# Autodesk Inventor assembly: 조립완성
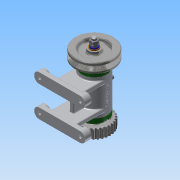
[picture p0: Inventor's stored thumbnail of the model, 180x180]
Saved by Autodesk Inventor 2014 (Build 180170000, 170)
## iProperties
Created: 2015-11
Part Number: 조립완성
Document SubType Name: Assembly
Designer: 27
Author: 27
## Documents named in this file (16)
- C:\Users\27\Desktop\451110V1019\조립완성.iam
- C:\Users\27\Desktop\451110V1019\1-본체.ipt
- C:\Users\27\Desktop\451110V1019\베어링 15 x 32 x 9.ipt
- C:\Users\27\Desktop\451110V1019\축.ipt
- C:\Users\27\Desktop\451110V1019\키 3 x 3 x 12.ipt
- C:\Users\27\Desktop\451110V1019\커버.ipt
- C:\Users\27\Desktop\451110V1019\오일 실 15 25 7.ipt
- C:\Users\27\Desktop\451110V1019\V벨트풀리.ipt
- C:\Users\27\Desktop\451110V1019\스퍼기어.ipt
- C:\Users\27\Desktop\451110V1019\와셔 8x17.ipt
- C:\Users\27\Desktop\451110V1019\스프링와셔 8.ipt
- C:\Users\27\Desktop\451110V1019\너트 M 8.ipt
- C:\Users\27\Desktop\451110V1019\볼트 M4 x 12.ipt
- C:\Users\27\Desktop\451110V1019\니플 M 6 x 0.75.ipt
- C:\Users\27\Desktop\451110V1019\볼트 M 6 x 8.ipt
- C:\Users\27\Desktop\451110V1019\와셔 6x11.5.ipt
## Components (12 placed, 4 different names)
1. 1-본체:1 — 각도:5, 각도:6, 각도:7, 각도:8, 각도:9, 각도:10
2. KS B 2023 6002 - 15 x 32 x 9:1
3. KS B 2023 6002 - 15 x 32 x 9:2
4. V벨트풀리:1 — 각도:3
5. ISO 4762 M4 x 12:1
6. ISO 4762 M4 x 12:3
7. ISO 4762 M4 x 12:4
8. ISO 4762 M4 x 12:5
9. ISO 4762 M4 x 12:2
10. ISO 4762 M4 x 12:6
11. ISO 4762 M4 x 12:7
12. ISO 4762 M4 x 12:8
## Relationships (7: Angle 7)
- 각도:3 [Angle]: V벨트풀리:1
- 각도:5 [Angle]: 1-본체:1
- 각도:6 [Angle]: 1-본체:1
- 각도:7 [Angle]: 1-본체:1
- 각도:8 [Angle]: 1-본체:1
- 각도:9 [Angle]: 1-본체:1
- 각도:10 [Angle]: 1-본체:1
